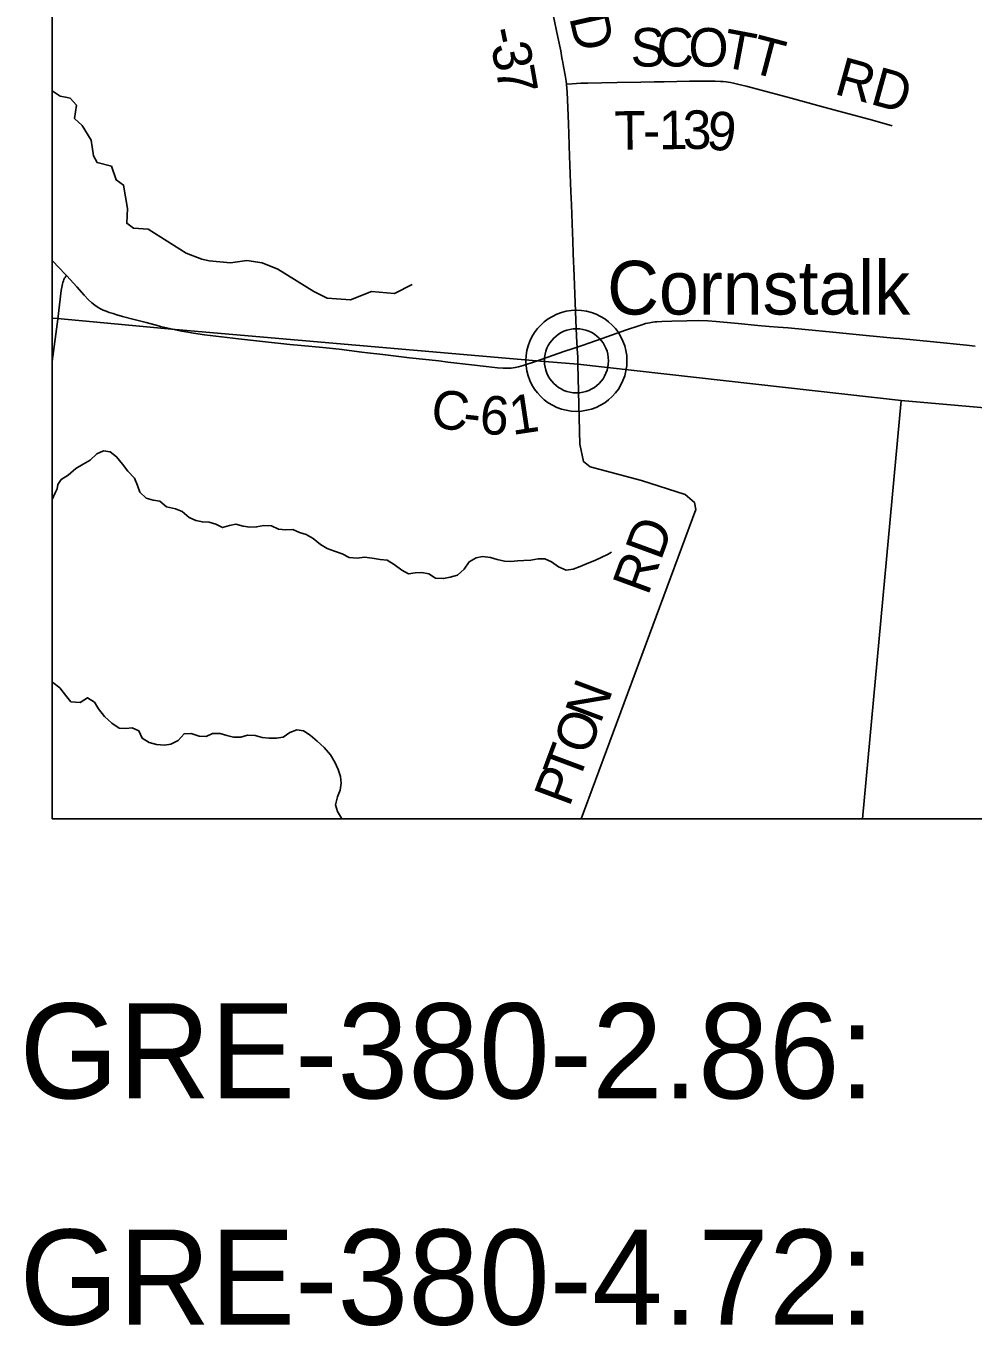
# Model space of a CAD drawing. Extents: x 0 to 34, y 0 to 22.
# Drawn here: x 9.499 to 10.893, y 13.559 to 15.473 of the extents above; entities that cross this region are included whole.
import ezdxf

# ---------------------------------------------------------------- set-up
doc = ezdxf.new("R2010")
doc.units = 0
for name, color, linetype in [('GM_X_Corporation', 7, 'Continuous'), ('GM_X_County_Road', 7, 'Continuous'), ('GM_X_County_Road_Text', 7, 'Continuous'), ('GM_X_Minor_River', 7, 'Continuous'), ('GM_X_Township_Road', 7, 'Continuous'), ('GM_X_Township_Road_Text', 7, 'Continuous'), ('GM_X_Unincorporated', 7, 'Continuous'), ('GM_X_Unincorporated_Location', 7, 'Continuous'), ('GM_X_Unincorporated_Text', 7, 'Continuous'), ('SH_Text', 7, 'Continuous')]:
    doc.layers.add(name, color=color, linetype=linetype)

msp = doc.modelspace()

# ---------------------------------------------------------------- linework, layer by layer
at = {"layer": 'GM_X_Corporation'}
for points in [[(16.3375, 14.3932), (16.3375, 21.1059), (9.5375, 21.1059), (9.5375, 15.0426), (9.5452, 15.0418), (9.7185, 15.0258), (10.2502, 14.9799), (10.3112, 14.9746), (10.787, 14.9212), (11.3129, 14.8754), (11.3292, 14.8742), (12.1361, 14.7923), (13.6754, 14.6095), (14.714, 14.5341), (15.778, 14.4476), (16.0263, 14.4243)], [(9.5375, 15.0426), (9.5375, 14.3059), (10.7302, 14.3059), (10.787, 14.9212), (10.3112, 14.9746), (10.2502, 14.9799), (9.7185, 15.0258), (9.5452, 15.0418)], [(9.5375, 15.0426), (9.5375, 14.3059), (10.7302, 14.3059), (10.787, 14.9212), (10.3112, 14.9746), (10.2502, 14.9799), (9.7185, 15.0258), (9.5452, 15.0418)], [(10.7302, 14.3059), (16.3375, 14.3059), (16.3375, 14.3932), (16.0263, 14.4243), (15.778, 14.4476), (14.714, 14.5341), (13.6754, 14.6095), (12.1361, 14.7923), (11.3292, 14.8742), (11.3129, 14.8754), (10.787, 14.9212)], [(10.7302, 14.3059), (15.7632, 14.3059), (15.778, 14.4476), (14.714, 14.5341), (13.6754, 14.6095), (12.1361, 14.7923), (11.3292, 14.8742), (11.3129, 14.8754), (10.787, 14.9212)]]:
    msp.add_lwpolyline(points, close=True, dxfattribs=at)
msp.add_lwpolyline([(9.5375, 21.1059), (9.5375, 15.0426), (9.5452, 15.0418), (9.7185, 15.0258), (10.2502, 14.9799), (10.3112, 14.9746), (10.787, 14.9212), (11.3129, 14.8754), (11.3292, 14.8742), (12.1361, 14.7923), (13.6754, 14.6095)], dxfattribs=at)
at = {"layer": 'GM_X_County_Road'}
msp.add_line((9.5454, 15.0412), (9.5375, 14.9786), dxfattribs=at)
for points in [[(9.5375, 15.1275), (9.5481, 15.1162), (9.5556, 15.1082), (9.5587, 15.105)], [(9.5587, 15.105), (9.5735, 15.0888), (9.5846, 15.0762), (9.591, 15.0695), (9.5959, 15.0649), (9.6002, 15.0615), (9.6048, 15.0584), (9.6085, 15.0562), (9.6123, 15.0544), (9.6168, 15.0526), (9.6214, 15.0511), (9.6269, 15.0493), (9.6326, 15.0475), (9.641, 15.0451), (9.6578, 15.0407), (9.6756, 15.036), (9.6884, 15.0327), (9.6904, 15.0322)], [(10.3101, 14.9999), (10.3191, 15.0029), (10.3272, 15.0057), (10.3471, 15.0127), (10.3811, 15.0247), (10.4023, 15.0319), (10.4068, 15.0334), (10.4107, 15.0345), (10.4138, 15.0352), (10.4168, 15.0359), (10.4217, 15.0367), (10.4247, 15.037), (10.4274, 15.0373), (10.4348, 15.0377), (10.4497, 15.0382), (10.4715, 15.0388), (10.4889, 15.0389), (10.5026, 15.0384), (10.515, 15.0375), (10.5472, 15.0345), (10.5763, 15.0317), (10.593, 15.0303), (10.606, 15.0292), (10.6208, 15.0281), (10.6456, 15.0259), (10.6864, 15.0221), (10.7358, 15.0169), (10.7766, 15.0133), (10.7846, 15.0125)], [(9.6904, 15.0322), (9.6967, 15.0305), (9.7187, 15.0253)], [(10.2504, 14.9794), (10.2308, 14.973), (10.2237, 14.971), (10.2191, 14.9699), (10.213, 14.9691), (10.2075, 14.9688), (10.2013, 14.9689), (10.1927, 14.9695), (10.1761, 14.9714), (10.1546, 14.9739), (10.1199, 14.9779), (10.1063, 14.9795), (10.0631, 14.9844), (10.0557, 14.9853), (10.0242, 14.989), (10.0014, 14.9916), (9.9933, 14.9926), (9.96, 14.9967), (9.9359, 14.9992), (9.9037, 15.0021), (9.8871, 15.0038), (9.8512, 15.0078), (9.8117, 15.0121), (9.7864, 15.0152), (9.7617, 15.0182), (9.7452, 15.0205), (9.7342, 15.0222), (9.7277, 15.0233), (9.7187, 15.0253)], [(10.2504, 14.9794), (10.2907, 14.9934), (10.3041, 14.9979), (10.3101, 14.9999)], [(10.7846, 15.0125), (10.8347, 15.0077), (10.8836, 15.0027), (10.8959, 15.0015)], [(10.3163, 14.3059), (10.485, 14.7612), (10.4829, 14.7715), (10.4691, 14.7828), (10.405, 14.8034), (10.3294, 14.8237), (10.3193, 14.8315), (10.3141, 14.8571), (10.3114, 14.9741)]]:
    msp.add_lwpolyline(points, dxfattribs=at)
at = {"layer": 'GM_X_Minor_River'}
msp.add_line((9.5375, 14.507), (9.5382, 14.5066), dxfattribs=at)
for points in [[(9.5375, 15.3772), (9.5491, 15.3692), (9.5595, 15.3673)], [(9.5595, 15.3673), (9.5638, 15.3664)], [(9.5638, 15.3664), (9.573, 15.3559), (9.5703, 15.3363), (9.5815, 15.3261), (9.5947, 15.3045), (9.598, 15.2816), (9.6035, 15.2716), (9.6246, 15.2662), (9.6314, 15.2459), (9.6423, 15.2384), (9.648, 15.2041), (9.6471, 15.1821), (9.6568, 15.175), (9.6788, 15.1733), (9.7346, 15.1382), (9.7576, 15.1293), (9.7685, 15.1271), (9.7996, 15.1238), (9.8239, 15.1274), (9.8466, 15.1238), (9.8696, 15.1145), (9.9227, 15.0817), (9.9423, 15.0718), (9.9764, 15.0694), (10.0074, 15.082), (10.0411, 15.0786), (10.0672, 15.092)], [(9.5503, 14.805), (9.5609, 14.8116), (9.5721, 14.8215), (9.5829, 14.8277), (9.593, 14.8335), (9.6031, 14.8431), (9.6127, 14.8474), (9.6225, 14.846), (9.6322, 14.8386), (9.6407, 14.8277), (9.6487, 14.8172), (9.6583, 14.8071), (9.663, 14.7963), (9.6662, 14.7867), (9.6758, 14.7777), (9.686, 14.7748), (9.6958, 14.773), (9.7058, 14.7651), (9.7187, 14.7621), (9.7288, 14.758), (9.7388, 14.749), (9.7486, 14.745), (9.7584, 14.7428), (9.7683, 14.7422), (9.7784, 14.7392), (9.7882, 14.7344), (9.7982, 14.7376), (9.8077, 14.7392), (9.8186, 14.7363), (9.8285, 14.7349), (9.8383, 14.7354), (9.849, 14.7374), (9.8604, 14.7367), (9.8705, 14.7322), (9.8815, 14.7312), (9.8914, 14.7313), (9.9012, 14.7272), (9.911, 14.7243), (9.9214, 14.7183), (9.9322, 14.7093), (9.9419, 14.7037), (9.9529, 14.6996), (9.9641, 14.6959), (9.9746, 14.6903), (9.9864, 14.6892), (9.997, 14.6908), (10.0084, 14.6894), (10.0201, 14.6876), (10.0307, 14.6865), (10.0408, 14.6802), (10.052, 14.6715), (10.0621, 14.6663), (10.0716, 14.6676), (10.0815, 14.6684), (10.0917, 14.6663), (10.1018, 14.6599), (10.1136, 14.6592), (10.1231, 14.6612), (10.1338, 14.6644), (10.1439, 14.6732), (10.1514, 14.6837), (10.1615, 14.6899), (10.171, 14.6919), (10.1824, 14.6901), (10.1922, 14.6875), (10.2031, 14.685), (10.2126, 14.6843), (10.2221, 14.6852), (10.2316, 14.6861), (10.2419, 14.6866), (10.2526, 14.6882), (10.2624, 14.6883), (10.2726, 14.6839), (10.2826, 14.6764), (10.2939, 14.6715), (10.3042, 14.6732), (10.3145, 14.6771), (10.3249, 14.6817), (10.336, 14.686), (10.3457, 14.6903), (10.3557, 14.6954), (10.3607, 14.6983)], [(9.5375, 14.7759), (9.5394, 14.7802), (9.5424, 14.7863), (9.5444, 14.7916), (9.5455, 14.7977), (9.5503, 14.805)], [(9.5382, 14.5066), (9.5484, 14.4986), (9.5569, 14.4877), (9.565, 14.478), (9.5786, 14.4768), (9.5891, 14.4838), (9.5995, 14.4774), (9.6057, 14.4674), (9.6142, 14.4561), (9.6253, 14.4467), (9.6357, 14.4392), (9.6456, 14.4389), (9.6551, 14.4398), (9.6649, 14.435), (9.6699, 14.4242), (9.68, 14.4179), (9.6909, 14.4153), (9.7027, 14.4142), (9.7122, 14.4155), (9.723, 14.4209), (9.7316, 14.431), (9.7419, 14.4314), (9.7535, 14.4273), (9.7638, 14.4271), (9.7734, 14.4314), (9.7844, 14.4314), (9.7942, 14.4285), (9.8044, 14.426), (9.815, 14.4257), (9.825, 14.4288), (9.836, 14.4282), (9.8465, 14.4256), (9.8567, 14.4246), (9.8674, 14.4243), (9.8773, 14.4259), (9.887, 14.4329), (9.8973, 14.4368), (9.9072, 14.4354), (9.9172, 14.4291), (9.9276, 14.42), (9.9376, 14.4106), (9.9468, 14.3998), (9.9534, 14.3893), (9.9581, 14.3782), (9.962, 14.3678), (9.9628, 14.3583), (9.9614, 14.348), (9.9574, 14.3379), (9.9544, 14.3265), (9.9572, 14.3166), (9.9634, 14.3065), (9.9638, 14.3059)]]:
    msp.add_lwpolyline(points, dxfattribs=at)
at = {"layer": 'GM_X_Township_Road'}
for points in [[(10.2944, 15.3867), (10.2938, 15.3914), (10.2925, 15.4), (10.2902, 15.4128), (10.289, 15.4189), (10.2878, 15.4256), (10.2859, 15.436), (10.2818, 15.4561), (10.2749, 15.489)], [(10.2944, 15.3867), (10.303, 15.3875), (10.3094, 15.3879), (10.3155, 15.3882), (10.3261, 15.3884), (10.3465, 15.3888), (10.369, 15.3892), (10.4037, 15.39), (10.4236, 15.3902), (10.4385, 15.3904), (10.4758, 15.3912), (10.4988, 15.3915), (10.5063, 15.3915), (10.5131, 15.3914), (10.5211, 15.391), (10.5252, 15.3907), (10.5293, 15.3903), (10.5324, 15.3898), (10.5361, 15.3893), (10.5405, 15.3884), (10.5463, 15.3871), (10.559, 15.384), (10.6052, 15.3717), (10.625, 15.3663), (10.6646, 15.3557), (10.6934, 15.3479), (10.7396, 15.3354), (10.7623, 15.329), (10.7741, 15.3257)], [(10.3101, 14.9999), (10.3097, 15.0062), (10.3087, 15.0273), (10.3074, 15.0651), (10.3058, 15.1043), (10.3045, 15.1378), (10.3038, 15.1564), (10.3034, 15.1682), (10.3023, 15.1955), (10.3017, 15.2092), (10.3011, 15.229), (10.3, 15.2545), (10.2994, 15.2687), (10.2989, 15.2805), (10.2978, 15.314), (10.2972, 15.3283), (10.2959, 15.3642), (10.2954, 15.3747), (10.2944, 15.3867)], [(9.5454, 15.0412), (9.5507, 15.0834), (9.5519, 15.0908), (9.5524, 15.0929), (9.553, 15.0951), (9.5538, 15.0976), (9.5546, 15.0995), (9.5555, 15.1012), (9.5565, 15.1026), (9.5571, 15.1033), (9.5576, 15.1041), (9.5587, 15.105)], [(10.3114, 14.9741), (10.3111, 14.9851), (10.3102, 14.9975), (10.3101, 14.9999)]]:
    msp.add_lwpolyline(points, dxfattribs=at)
at = {"layer": 'GM_X_Unincorporated'}
for radius in [0.0744, 0.0472]:
    msp.add_circle((10.3091, 14.9798), radius, dxfattribs=at)
at = {"layer": 'GM_X_Unincorporated_Location'}
msp.add_line((10.3091, 14.9798), (10.3091, 14.9798), dxfattribs=at)

# ---------------------------------------------------------------- texts
at = {"layer": 'GM_X_County_Road_Text'}
for s, height, rotation, p in [('C', 0.0568, 351.9019, (10.0925, 14.8828)), ('6', 0.0568, 354.9505, (10.1651, 14.8732)), ('1', 0.0568, 8.5238, (10.2147, 14.8705)), ('-', 0.0568, 353.5003, (10.1404, 14.876)), ('RD', 0.05682, 69.8498, (10.4143, 14.6329)), ('N', 0.0568, 69.4966, (10.3443, 14.4443)), ('O', 0.0568, 69.4955, (10.3268, 14.3975)), ('T', 0.0568, 69.4957, (10.3119, 14.3577)), ('P', 0.0568, 69.4946, (10.2985, 14.3218))]:
    msp.add_text(s, height=height, rotation=rotation, dxfattribs=at).set_placement(p)
at = {"layer": 'GM_X_Township_Road_Text'}
for s, height, rotation, p in [('RD', 0.05682, 282.8473, (10.2861, 15.5387)), ('-', 0.0568, 281.7761, (10.1783, 15.4663)), ('S', 0.0568, 359.9857, (10.3889, 15.4128)), ('C', 0.0568, 359.9863, (10.4272, 15.4128)), ('O', 0.0568, 359.7869, (10.4739, 15.4128)), ('T', 0.0568, 349.349, (10.5211, 15.4129)), ('T', 0.0568, 345.2736, (10.5619, 15.4053)), ('3', 0.0568, 281.659, (10.183, 15.4435)), ('RD', 0.05682, 344.5284, (10.6869, 15.3729)), ('7', 0.0568, 279.9264, (10.19, 15.4097)), ('T', 0.0568, 0.6343, (10.3651, 15.2902)), ('1', 0.0568, 0.6422, (10.4309, 15.291)), ('3', 0.0568, 0.6509, (10.4659, 15.2913)), ('9', 0.0568, 353.7245, (10.4991, 15.2918)), ('-', 0.0568, 0.6323, (10.4076, 15.2907))]:
    msp.add_text(s, height=height, rotation=rotation, dxfattribs=at).set_placement(p)
at = {"layer": 'GM_X_Unincorporated_Text'}
msp.add_text('Cornstalk', height=0.07898, rotation=0, dxfattribs=at).set_placement((10.3543, 15.0479))
at = {"layer": 'SH_Text'}
for s, p in [('GRE-380-2.86:', (9.4893, 13.8943)), ('GRE-380-4.72:', (9.4893, 13.5613))]:
    msp.add_text(s, height=0.14, dxfattribs=at).set_placement(p)

doc.saveas('drawing.dxf')
